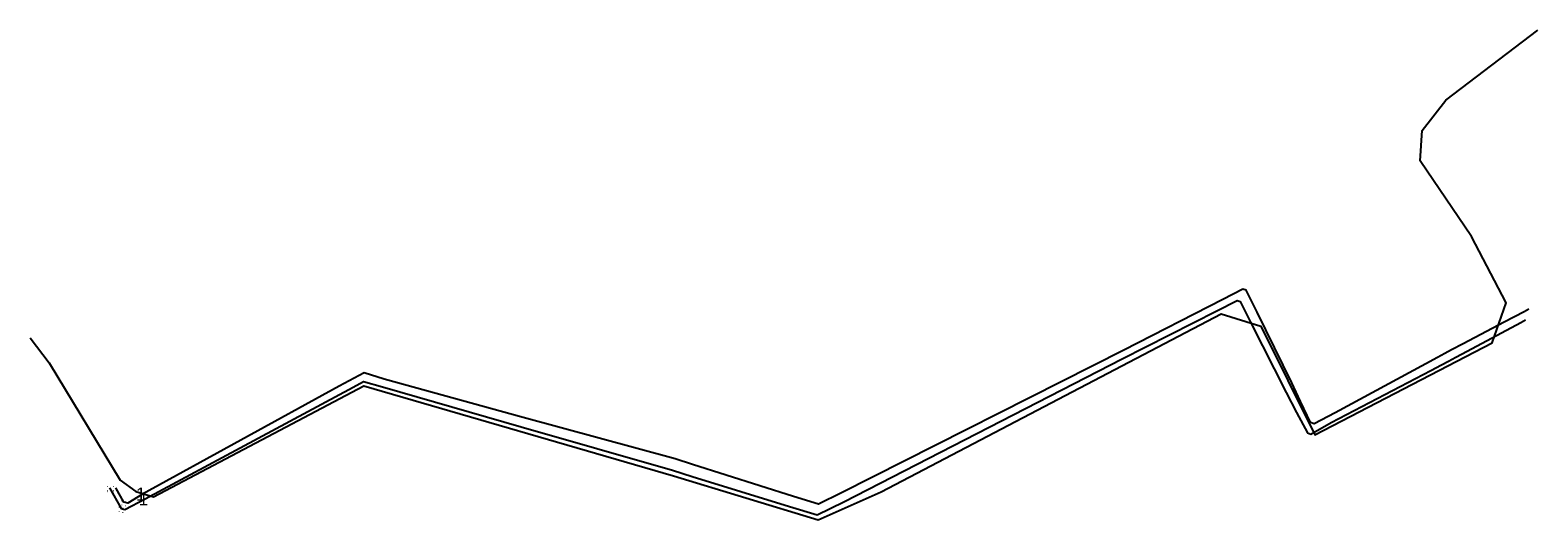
# Model space of a CAD drawing. Extents: x -444513 to -444229, y -1122290 to -1122109.
# Drawn here: x -444286.6 to -444229.1, y -1122241.9 to -1122223.2 of the extents above; entities that cross this region are included whole.
import ezdxf

# ---------------------------------------------------------------- set-up
doc = ezdxf.new("R2010")
doc.units = 0
for name, color, linetype in [('Jiné vedení', 7, 'Continuous'), ('Kabel tepelného rozvodu - linie', 7, 'Continuous'), ('Potrubí tepelného rozvodu - linie', 7, 'Continuous'), ('Počáteční_koncový bod potrubí tepelného rozvodu', 7, 'Continuous'), ('Vnitřní bod potrubí tepelného rozvodu', 7, 'Continuous')]:
    doc.layers.add(name, color=color, linetype=linetype)

msp = doc.modelspace()

# ---------------------------------------------------------------- linework, layer by layer
at = {"layer": 'Jiné vedení'}
msp.add_lwpolyline([(-444286.6, -1122234.93), (-444285.87, -1122235.89), (-444283.17, -1122240.35), (-444282.57, -1122240.78), (-444281.9, -1122240.99), (-444273.88, -1122236.76), (-444262.08, -1122240.18), (-444256.57, -1122241.86), (-444254.17, -1122240.8), (-444241.21, -1122234.02), (-444239.7, -1122234.49), (-444237.64, -1122238.63), (-444230.88, -1122235.12), (-444230.35, -1122233.6), (-444231.67, -1122231.08), (-444233.62, -1122228.19), (-444233.55, -1122227.04), (-444232.65, -1122225.89), (-444229.14, -1122223.22)], dxfattribs=at)
at = {"layer": 'Kabel tepelného rozvodu - linie'}
msp.add_lwpolyline([(-444286.6, -1122234.93), (-444285.87, -1122235.89), (-444283.17, -1122240.35), (-444282.57, -1122240.78), (-444281.9, -1122240.99), (-444273.88, -1122236.76), (-444262.08, -1122240.18), (-444256.57, -1122241.86), (-444254.17, -1122240.8), (-444241.21, -1122234.02), (-444239.7, -1122234.49), (-444237.64, -1122238.63), (-444230.88, -1122235.12), (-444230.35, -1122233.6), (-444231.67, -1122231.08), (-444233.62, -1122228.19), (-444233.55, -1122227.04), (-444232.65, -1122225.89), (-444229.14, -1122223.22)], dxfattribs=at)
at = {"layer": 'Potrubí tepelného rozvodu - linie'}
for points in [[(-444229.48, -1122233.84), (-444229.66, -1122233.94), (-444230.42, -1122234.33), (-444231.98, -1122235.16), (-444232.43, -1122235.39), (-444232.69, -1122235.53), (-444232.96, -1122235.68), (-444233.41, -1122235.92), (-444236.87, -1122237.79), (-444237.67, -1122238.21), (-444237.8, -1122238.15), (-444238.19, -1122237.35), (-444238.52, -1122236.64), (-444239.84, -1122233.95), (-444240.26, -1122233.12), (-444240.38, -1122233.08), (-444241.15, -1122233.47), (-444244.92, -1122235.4), (-444255.68, -1122240.83), (-444256.56, -1122241.27), (-444257.51, -1122240.97), (-444261.36, -1122239.75), (-444262.02, -1122239.54), (-444267.81, -1122237.96), (-444273.11, -1122236.51), (-444273.87, -1122236.27), (-444274.82, -1122236.77), (-444282.32, -1122240.88), (-444282.88, -1122241.22), (-444283.03, -1122241.19), (-444283.34, -1122240.64)], [(-444229.48, -1122233.84), (-444229.66, -1122233.94), (-444230.42, -1122234.33), (-444231.98, -1122235.16), (-444232.43, -1122235.39), (-444232.69, -1122235.53), (-444232.96, -1122235.68), (-444233.41, -1122235.92), (-444236.87, -1122237.79), (-444237.67, -1122238.21), (-444237.8, -1122238.15), (-444238.19, -1122237.35), (-444238.52, -1122236.64), (-444239.84, -1122233.95), (-444240.26, -1122233.12), (-444240.38, -1122233.08), (-444241.15, -1122233.47), (-444244.92, -1122235.4), (-444255.68, -1122240.83), (-444256.56, -1122241.27), (-444257.51, -1122240.97), (-444261.36, -1122239.75), (-444262.02, -1122239.54), (-444267.81, -1122237.96), (-444273.11, -1122236.51), (-444273.87, -1122236.27), (-444274.82, -1122236.77), (-444282.32, -1122240.88), (-444282.88, -1122241.22), (-444283.03, -1122241.19), (-444283.34, -1122240.64)], [(-444283.57, -1122240.64), (-444283.13, -1122241.43), (-444282.99, -1122241.47), (-444282.22, -1122241.06), (-444274.29, -1122236.81), (-444273.89, -1122236.59), (-444273.17, -1122236.8), (-444267.89, -1122238.32), (-444262.12, -1122239.97), (-444261.37, -1122240.21), (-444257.66, -1122241.35), (-444256.61, -1122241.67), (-444255.59, -1122241.18), (-444244.98, -1122235.73), (-444241.37, -1122233.91), (-444240.6, -1122233.51), (-444240.48, -1122233.55), (-444240.09, -1122234.33), (-444238.73, -1122237.01), (-444238.34, -1122237.78), (-444237.92, -1122238.55), (-444237.79, -1122238.6), (-444237.02, -1122238.16), (-444233.22, -1122236.18), (-444232.81, -1122235.96), (-444232.54, -1122235.815), (-444232.27, -1122235.67), (-444231.84, -1122235.44), (-444230.53, -1122234.74), (-444229.79, -1122234.35), (-444229.61, -1122234.25)], [(-444283.57, -1122240.64), (-444283.13, -1122241.43), (-444282.99, -1122241.47), (-444282.22, -1122241.06), (-444274.29, -1122236.81), (-444273.89, -1122236.59), (-444273.17, -1122236.8), (-444267.89, -1122238.32), (-444262.12, -1122239.97), (-444261.37, -1122240.21), (-444257.66, -1122241.35), (-444256.61, -1122241.67), (-444255.59, -1122241.18), (-444244.98, -1122235.73), (-444241.37, -1122233.91), (-444240.6, -1122233.51), (-444240.48, -1122233.55), (-444240.09, -1122234.33), (-444238.73, -1122237.01), (-444238.34, -1122237.78), (-444237.92, -1122238.55), (-444237.79, -1122238.6), (-444237.02, -1122238.16), (-444233.22, -1122236.18), (-444232.81, -1122235.96), (-444232.54, -1122235.815), (-444232.27, -1122235.67), (-444231.84, -1122235.44), (-444230.53, -1122234.74), (-444229.79, -1122234.35), (-444229.61, -1122234.25)]]:
    msp.add_lwpolyline(points, dxfattribs=at)

# ---------------------------------------------------------------- texts
at = {"layer": 'Počáteční_koncový bod potrubí tepelného rozvodu'}
for p in [(-444283.695, -1122240.765), (-444283.695, -1122240.765), (-444283.465, -1122240.765), (-444283.465, -1122240.765)]:
    msp.add_text(';', height=0.25, dxfattribs=at).set_placement(p)
at = {"layer": 'Vnitřní bod potrubí tepelného rozvodu'}
for s, height, p in [('1', 0.5, (-444282.57, -1122241.13)), ('1', 0.5, (-444282.57, -1122241.13)), ('1', 0.5, (-444282.47, -1122241.31)), ('1', 0.5, (-444282.47, -1122241.31)), (':', 0.25, (-444283.255, -1122241.555)), (':', 0.25, (-444283.255, -1122241.555)), (':', 0.25, (-444283.155, -1122241.315)), (':', 0.25, (-444283.155, -1122241.315)), (':', 0.25, (-444283.115, -1122241.595)), (':', 0.25, (-444283.115, -1122241.595)), (':', 0.25, (-444283.005, -1122241.345)), (':', 0.25, (-444283.005, -1122241.345))]:
    msp.add_text(s, height=height, dxfattribs=at).set_placement(p)

doc.saveas('drawing.dxf')
